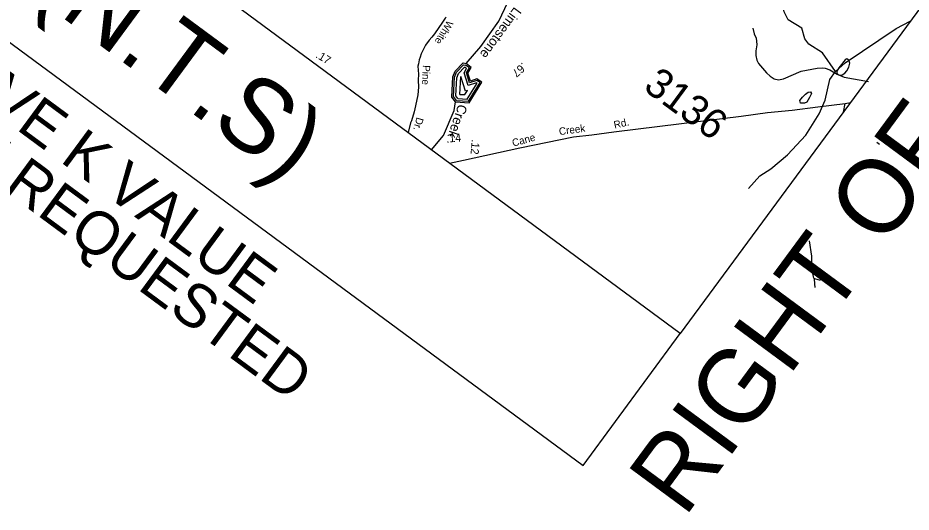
# Model space of a CAD drawing. Extents: x 945666 to 965748, y 644452 to 663300.
# Drawn here: x 953745 to 955557, y 656118 to 657119 of the extents above; entities that cross this region are included whole.
import ezdxf

# ---------------------------------------------------------------- set-up
doc = ezdxf.new("R2010")
doc.units = 0
for name, color, linetype in [('Exist Hydrographic Buffer Line', 7, 'Continuous'), ('Exist Hydrographic Creek Single Shore', 7, 'Continuous'), ('Exist Hydrographic Lake Shore', 7, 'Continuous'), ('Exist Hydrographic Misc Water Feature', 7, 'Continuous'), ('Exist Hydrographic Pond Under 1500 Sq Ft', 7, 'Continuous'), ('Exist Road Secondary Mileage Tenths English Label', 7, 'Continuous'), ('Exist Road Secondary Type 51 Attributed', 7, 'Continuous'), ('Exist Road Secondary Type 51 Label', 7, 'Continuous'), ('Old_Level_1', 7, 'Continuous'), ('Old_Level_38', 7, 'Continuous'), ('Prop Paved Shoulder', 7, 'Continuous'), ('Sheet Data Field CELL', 7, 'Continuous'), ('Sheet Title CELL', 7, 'Continuous')]:
    doc.layers.add(name, color=color, linetype=linetype)

msp = doc.modelspace()

# ---------------------------------------------------------------- linework, layer by layer
at = {"layer": 'Exist Hydrographic Buffer Line'}
for p, q in [((954655.1, 657016.6), (954651.9, 657019.1)), ((954660.7, 657017.9), (954653.2, 657023.7)), ((954641.5, 656964.3), (954643.4, 657000.6))]:
    msp.add_line(p, q, dxfattribs=at)
for points in [[(954634.6, 656951.5), (954628.4, 656959.9), (954630.3, 656999), (954634.7, 657009.3), (954649.1, 657024.3), (954653.2, 657023.7)], [(954637.5, 656955.6), (954633.2, 656961.3), (954635.1, 656998), (954638.7, 657006.6), (954650.8, 657019.2), (954651.9, 657019.1)], [(954634.6, 656951.5), (954658.7, 656950.2), (954682.4, 656988), (954675.7, 656992.4), (954661.2, 656987.6), (954655, 657007.6), (954660.7, 657017.9)], [(954637.5, 656955.6), (954656.5, 656954.6), (954676.6, 656986.8), (954675.1, 656987.8), (954658.4, 656982.2), (954650.4, 657008), (954655.1, 657016.6)], [(954641.5, 656964.3), (954651.7, 656963.8), (954657.1, 656972.4), (954652.6, 656970.9), (954643.4, 657000.6)]]:
    msp.add_lwpolyline(points, dxfattribs=at)
at = {"layer": 'Exist Hydrographic Creek Single Shore'}
for points in [[(955403.4, 657010.4), (955376.7, 657048.1), (955349.4, 657065.9), (955341.2, 657076.5), (955334.8, 657098.1), (955307.2, 657115.6), (955299.4, 657131.8), (955290.1, 657177.7), (955290.2, 657203.9), (955299, 657248.2), (955316.3, 657283.9), (955322.5, 657316.2), (955322.2, 657352.4), (955378.1, 657422.9), (955395.6, 657471.2), (955408.4, 657494.3), (955443.7, 657542.3), (955455.3, 657581.3), (955478.9, 657623.4), (955486.5, 657669.6), (955491, 657704.9), (955516.3, 657731.7)], [(954654.1, 657026.9), (954684.1, 657061.3), (954720.4, 657112.4), (954738.9, 657151.4)], [(955403.4, 657010.4), (955423, 657028.1), (955526.7, 657097.9), (955555, 657112.7), (955555.4, 657112.8)], [(955226.9, 656773.6), (955250, 656799.3), (955272.2, 656813.4), (955305.8, 656841.9), (955342.9, 656881.7), (955370.4, 656925.1), (955382.4, 656952.4), (955392.1, 656994.4), (955403.4, 657010.4)], [(954583.9, 656852), (954608.6, 656880.6), (954629.7, 656931.6), (954632.4, 656948.9)]]:
    msp.add_lwpolyline(points, dxfattribs=at)
at = {"layer": 'Exist Hydrographic Lake Shore'}
msp.add_line((954664.4, 657019), (954654.1, 657026.9), dxfattribs=at)
for points in [[(954632.4, 656948.9), (954625, 656958.9), (954627.1, 656999.8), (954631.9, 657011.1), (954647.9, 657027.9), (954654.1, 657026.9)], [(954632.4, 656948.9), (954660.2, 656947.4), (954686.1, 656988.8), (954676.1, 656995.4), (954663, 656991), (954657.9, 657007.3), (954664.4, 657019)]]:
    msp.add_lwpolyline(points, dxfattribs=at)
at = {"layer": 'Exist Hydrographic Misc Water Feature'}
msp.add_line((955487.5, 656867.6), (955492.7, 656863.2), dxfattribs=at)
for points in [[(955236, 657098.7), (955238.7, 657087), (955242.3, 657078.2), (955243.4, 657072), (955243.5, 657064.6), (955241.7, 657052.8), (955242.1, 657043.2), (955243.9, 657033.8), (955247.5, 657026.6), (955263.4, 657008.1), (955270.9, 657000.9), (955278.7, 656995.7), (955287.8, 656993.8), (955297.9, 656995.7), (955333.7, 657011.1), (955366.2, 657017.4), (955377.3, 657018), (955382.1, 657017.4), (955391.8, 657014.1), (955406.8, 657005.5), (955421.2, 656999.4), (955470.6, 656990.4)], [(955360.6, 656590.3), (955359.3, 656592), (955356.7, 656604.6), (955355.4, 656617.2), (955355.6, 656636.3), (955350.4, 656667.3)], [(955372.9, 656587.1), (955361.3, 656590.4), (955360.6, 656590.3)], [(955362.4, 656572.8), (955361.4, 656580.4), (955360.6, 656590.3)]]:
    msp.add_lwpolyline(points, dxfattribs=at)
at = {"layer": 'Exist Hydrographic Pond Under 1500 Sq Ft'}
for points in [[(955426.1, 657036.6), (955423.1, 657034.1), (955410, 657017.9), (955405.9, 657011.5), (955406.4, 657007.2), (955409.8, 657003.9), (955412.4, 657003.1), (955416.9, 657004.1), (955422.1, 657007.3), (955426.4, 657011.9), (955430.3, 657019.4), (955432.3, 657027.7), (955430.5, 657033.8), (955426.1, 657036.6)], [(955354.6, 656965.7), (955350.9, 656958), (955345, 656948.1), (955340.4, 656946.4), (955332.6, 656946.6), (955331.3, 656951.7), (955336.4, 656958.9), (955342.3, 656964.8), (955347.8, 656968.4), (955352.4, 656969.1), (955354.6, 656965.7)]]:
    msp.add_lwpolyline(points, dxfattribs=at)
at = {"layer": 'Exist Road Secondary Type 51 Attributed'}
msp.add_line((954541.6, 656906.6), (954536.6, 656886.9), dxfattribs=at)
for points in [[(954613.7, 657120.9), (954611.7, 657118.8), (954606, 657110.4), (954590.2, 657086.8), (954584.6, 657079.9), (954579.1, 657074), (954572.1, 657064.2), (954563.1, 657046.7), (954561, 657039.4), (954559.2, 657034.4), (954557.7, 657026.3), (954556.5, 657021.6), (954557.3, 657004.9), (954556.6, 656993)], [(954556.6, 656993), (954557.3, 656978.9), (954556.5, 656963.5), (954551.3, 656940.7), (954548.8, 656929.1), (954543.5, 656910.6), (954541.6, 656906.6)], [(954620.6, 656825), (954649, 656830.7), (954763.3, 656855.8), (954871.8, 656878.3), (954908.9, 656882.4), (954953.6, 656888), (955047.3, 656899.8), (955212.2, 656920), (955265.4, 656927.3), (955315.7, 656932), (955367.6, 656939), (955423, 656945.6)], [(955419.4, 656928.3), (955423, 656945.6)], [(955423, 656945.6), (955433.6, 656947.6)]]:
    msp.add_lwpolyline(points, dxfattribs=at)
at = {"layer": 'Old_Level_1'}
for points in [[(953667.4, 661172.9), (956829.7, 658840.6), (955088.6, 656479.8), (951926.2, 658812.1)], [(951728.9, 658544.5), (954891.3, 656212.2), (955088.6, 656479.8), (951926.2, 658812.1)]]:
    msp.add_lwpolyline(points, close=True, dxfattribs=at)

# ---------------------------------------------------------------- texts
at = {"layer": 'Exist Road Secondary Mileage Tenths English Label'}
for s, rotation, p in [('.17', 328.9959, (954347.8, 657039.9)), ('.67', 220.79, (954768.7, 657029.7)), ('.14', 5.0764, (954614.5, 656866.3)), ('.12', 265.2506, (954665.7, 656873.2))]:
    msp.add_text(s, height=16.24, rotation=rotation, dxfattribs=at).set_placement(p)
at = {"layer": 'Exist Road Secondary Type 51 Label'}
for s, rotation, p in [('White', 239.0646, (954616.2, 657115.3)), ('Pine', 266.9657, (954566.5, 657023.8)), ('Dr.', 254.4789, (954553.9, 656918.8)), ('Creek', 7.5949, (954843.5, 656881.5)), ('Rd.', 12.6712, (954955.4, 656894.7)), ('Cane', 15.462, (954749.7, 656858.2))]:
    msp.add_text(s, height=15, rotation=rotation, dxfattribs=at).set_placement(p)
at = {"layer": 'Old_Level_1'}
msp.add_text('3136', height=60, rotation=323.5908, dxfattribs=at).set_placement((955011.2, 656974.9))
at = {"layer": 'Old_Level_38'}
msp.add_text('(N.T.S)', height=150, rotation=323.5908, dxfattribs=at).set_placement((953773.3, 657165.5))
at = {"layer": 'Prop Paved Shoulder'}
for s, rotation, p in [('Limestone', 233.6808, (954752.1, 657142.6)), ('Creek', 251.3572, (954638.7, 656945.7))]:
    msp.add_text(s, height=19.49, rotation=rotation, dxfattribs=at).set_placement(p)
at = {"layer": 'Sheet Data Field CELL'}
for s, p in [('1. DESIGN EXCEPTIONS FOR VERTICAL CURVE K VALUE', (951636, 658446)), (' AND STOPPING SIGHT DISTANCE HAVE BEEN REQUESTED', (951567.9, 658353.7))]:
    msp.add_text(s, height=87.501, rotation=323.5908, dxfattribs=at).set_placement(p)
at = {"layer": 'Sheet Title CELL'}
msp.add_text('RIGHT OF WAY PLANS', height=150, rotation=53.5908, dxfattribs=at).set_placement((955097, 656104.3))

doc.saveas('drawing.dxf')
